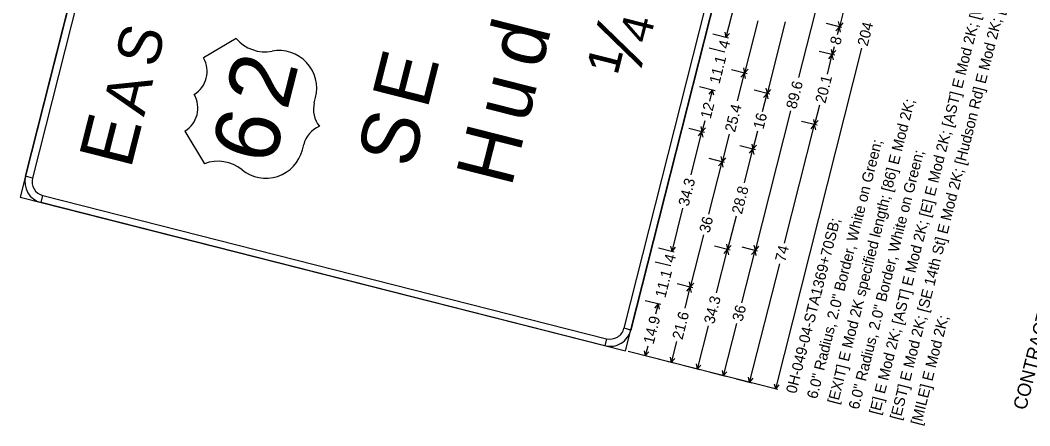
# Model space of a CAD drawing. Extents: x 670003 to 670131, y 737835 to 738003.
# Drawn here: x 670006.28 to 670053.15, y 737850.17 to 737868.98 of the extents above; entities that cross this region are included whole.
import ezdxf

# ---------------------------------------------------------------- set-up
doc = ezdxf.new("R2010")
doc.units = 0
doc.layers.add('R_SIGN', color=7, linetype='Continuous')

msp = doc.modelspace()

# ---------------------------------------------------------------- linework, layer by layer
at = {"layer": 'R_SIGN'}
for p, q in [((670014.634, 737893.727), (670006.276, 737860.771)), ((670034.386, 737853.641), (670042.744, 737886.598)), ((670042.425, 737866.321), (670044.064, 737872.783)), ((670044.932, 737871.133), (670044.308, 737868.675)), ((670039.547, 737870.187), (670039.038, 737868.182)), ((670040.519, 737868.947), (670039.903, 737866.52)), ((670041.794, 737868.904), (670040.951, 737865.581)), ((670044.429, 737868.645), (670043.704, 737868.828)), ((670044.255, 737868.919), (670044.308, 737868.675)), ((670044.471, 737868.864), (670044.308, 737868.675)), ((670039.159, 737868.152), (670038.434, 737868.335)), ((670038.985, 737868.426), (670039.038, 737868.182)), ((670039.201, 737868.371), (670039.038, 737868.182)), ((670044.145, 737868.486), (670044.308, 737868.675)), ((670044.217, 737868.317), (670044.308, 737868.675)), ((670044.361, 737868.432), (670044.308, 737868.675)), ((670016.302, 737868.135), (670014.783, 737867.231)), ((670038.995, 737867.505), (670038.27, 737867.689)), ((670045.343, 737867.682), (670041.335, 737851.879)), ((670044.101, 737867.352), (670043.376, 737867.536)), ((670043.753, 737866.485), (670043.98, 737867.383)), ((670043.817, 737867.194), (670043.98, 737867.383)), ((670043.927, 737867.626), (670043.98, 737867.383)), ((670044.071, 737867.741), (670043.98, 737867.383)), ((670044.143, 737867.571), (670043.98, 737867.383)), ((670044.034, 737867.139), (670043.98, 737867.383)), ((670040.024, 737866.49), (670039.299, 737866.674)), ((670039.578, 737865.24), (670039.903, 737866.52)), ((670039.74, 737866.332), (670039.903, 737866.52)), ((670039.85, 737866.764), (670039.903, 737866.52)), ((670040.066, 737866.709), (670039.903, 737866.52)), ((670039.956, 737866.277), (670039.903, 737866.52)), ((670038.541, 737865.712), (670037.815, 737865.896)), ((670038.257, 737865.554), (670038.42, 737865.743)), ((670038.289, 737865.228), (670038.42, 737865.743)), ((670038.473, 737865.499), (670038.42, 737865.743)), ((670041.072, 737865.55), (670040.347, 737865.734)), ((670040.74, 737864.748), (670040.951, 737865.581)), ((670040.788, 737865.392), (670040.951, 737865.581)), ((670040.898, 737865.824), (670040.951, 737865.581)), ((670041.114, 737865.769), (670040.951, 737865.581)), ((670041.004, 737865.337), (670040.951, 737865.581)), ((670019.93, 737865.152), (670019.992, 737865.394)), ((670043.385, 737865.033), (670043.157, 737864.136)), ((670042.032, 737864.77), (670040.393, 737858.308)), ((670037.875, 737864.048), (670037.928, 737863.804)), ((670038.058, 737864.319), (670037.928, 737863.804)), ((670041.762, 737858.637), (670043.157, 737864.136)), ((670043.278, 737864.105), (670042.553, 737864.289)), ((670042.994, 737863.947), (670043.157, 737864.136)), ((670043.104, 737864.379), (670043.157, 737864.136)), ((670043.32, 737864.324), (670043.157, 737864.136)), ((670043.21, 737863.892), (670043.157, 737864.136)), ((670013.923, 737863.838), (670014.827, 737862.319)), ((670038.049, 737863.774), (670037.324, 737863.957)), ((670037.42, 737861.802), (670037.928, 737863.804)), ((670037.765, 737863.615), (670037.928, 737863.804)), ((670038.091, 737863.993), (670037.928, 737863.804)), ((670037.981, 737863.561), (670037.928, 737863.804)), ((670039.186, 737863.694), (670038.862, 737862.414)), ((670040.507, 737863.828), (670040.295, 737862.996)), ((670019.377, 737862.971), (670019.439, 737863.213)), ((670040.416, 737862.965), (670039.691, 737863.149)), ((670040.242, 737863.239), (670040.295, 737862.996)), ((670040.458, 737863.184), (670040.295, 737862.996)), ((670038.808, 737862.657), (670038.862, 737862.414)), ((670039.902, 737861.444), (670040.295, 737862.996)), ((670040.132, 737862.807), (670040.295, 737862.996)), ((670040.349, 737862.752), (670040.295, 737862.996)), ((670038.246, 737859.987), (670038.862, 737862.414)), ((670038.982, 737862.383), (670038.257, 737862.567)), ((670038.699, 737862.225), (670038.862, 737862.414)), ((670039.024, 737862.602), (670038.862, 737862.414)), ((670038.915, 737862.17), (670038.862, 737862.414)), ((670006.845, 737861.658), (670006.522, 737861.74)), ((670006.276, 737860.771), (670034.386, 737853.641)), ((670007.245, 737860.525), (670007.327, 737860.848)), ((670037.03, 737860.262), (670036.522, 737858.26)), ((670039.509, 737859.894), (670039.115, 737858.343)), ((670038.002, 737859.024), (670037.387, 737856.598)), ((670036.469, 737858.503), (670036.522, 737858.26)), ((670036.685, 737858.448), (670036.522, 737858.26)), ((670039.236, 737858.312), (670038.511, 737858.496)), ((670039.062, 737858.587), (670039.115, 737858.343)), ((670039.278, 737858.532), (670039.115, 737858.343)), ((670040.513, 737858.277), (670039.788, 737858.461)), ((670040.339, 737858.552), (670040.393, 737858.308)), ((670040.556, 737858.497), (670040.393, 737858.308)), ((670036.643, 737858.229), (670035.918, 737858.413)), ((670038.608, 737856.341), (670039.115, 737858.343)), ((670038.952, 737858.154), (670039.115, 737858.343)), ((670039.169, 737858.099), (670039.115, 737858.343)), ((670039.777, 737855.881), (670040.393, 737858.308)), ((670040.23, 737858.119), (670040.393, 737858.308)), ((670040.446, 737858.064), (670040.393, 737858.308)), ((670036.479, 737857.583), (670035.754, 737857.767)), ((670041.521, 737857.684), (670040.126, 737852.186)), ((670037.507, 737856.567), (670036.782, 737856.751)), ((670037.141, 737855.629), (670037.387, 737856.598)), ((670037.224, 737856.409), (670037.387, 737856.598)), ((670037.333, 737856.841), (670037.387, 737856.598)), ((670037.549, 737856.787), (670037.387, 737856.598)), ((670037.44, 737856.354), (670037.387, 737856.598)), ((670036.024, 737855.79), (670035.299, 737855.974)), ((670035.74, 737855.632), (670035.903, 737855.82)), ((670035.787, 737855.364), (670035.903, 737855.82)), ((670035.956, 737855.577), (670035.903, 737855.82)), ((670034.632, 737854.611), (670034.309, 737854.693)), ((670038.217, 737854.801), (670037.709, 737852.799)), ((670039.533, 737854.919), (670038.918, 737852.492)), ((670033.499, 737854.21), (670033.417, 737853.887)), ((670035.408, 737853.867), (670035.292, 737853.412)), ((670036.746, 737854.074), (670036.501, 737853.105)), ((670034.386, 737853.641), (670034.386, 737853.641)), ((670041.455, 737851.848), (670034.507, 737853.611)), ((670035.413, 737853.381), (670034.688, 737853.565)), ((670035.239, 737853.655), (670035.292, 737853.412)), ((670035.455, 737853.6), (670035.292, 737853.412)), ((670036.447, 737853.349), (670036.501, 737853.105)), ((670036.664, 737853.294), (670036.501, 737853.105)), ((670036.622, 737853.074), (670035.896, 737853.258)), ((670037.83, 737852.768), (670037.105, 737852.952)), ((670037.656, 737853.042), (670037.709, 737852.799)), ((670037.872, 737852.987), (670037.709, 737852.799)), ((670039.038, 737852.461), (670038.313, 737852.645)), ((670038.864, 737852.736), (670038.918, 737852.492)), ((670039.08, 737852.681), (670038.918, 737852.492)), ((670040.247, 737852.155), (670039.522, 737852.339)), ((670040.073, 737852.429), (670040.126, 737852.186)), ((670040.289, 737852.374), (670040.126, 737852.186)), ((670041.281, 737852.123), (670041.335, 737851.879)), ((670041.497, 737852.068), (670041.335, 737851.879))]:
    msp.add_line(p, q, dxfattribs=at)
for points in [[(670014.712, 737892.676), (670006.845, 737861.658), (670006.522, 737861.74), (670014.389, 737892.758), (670014.712, 737892.676)], [(670034.309, 737854.693), (670042.175, 737885.711), (670042.499, 737885.629), (670034.632, 737854.611), (670034.309, 737854.693)], [(670007.327, 737860.848), (670033.499, 737854.21), (670033.417, 737853.887), (670007.245, 737860.525), (670007.327, 737860.848)]]:
    msp.add_lwpolyline(points, close=True, dxfattribs=at)
for centre, radius, start, end in [((670017.641, 737869.263), 1.75, 220.1058, 280.7786), ((670018.295, 737865.824), 1.75, 345.7686, 100.779), ((670013.703, 737866.602), 1.25, 301.3415, 30.1958), ((670013.273, 737864.906), 1.25, 301.3415, 30.1958), ((670021.142, 737864.844), 1.25, 165.7688, 218.8986), ((670020.65, 737862.906), 1.25, 112.6384, 165.7688), ((670017.681, 737863.401), 1.75, 230.7582, 345.7686), ((670015.467, 737860.69), 1.75, 50.7581, 111.4314), ((670007.491, 737861.494), 1, 165.7688, 255.7684), ((670007.491, 737861.494), 0.667, 165.7688, 255.7684), ((670033.662, 737854.857), 0.667, 255.7684, 345.7686), ((670033.662, 737854.857), 1, 255.7684, 345.7686)]:
    msp.add_arc(centre, radius, start, end, dxfattribs=at)

# ---------------------------------------------------------------- texts
for s, height, p in [('CONTRACTOR SHALL BE RESPONSIBLE FOR FIELD VERIFICATION OF', 0.625, (670052.971, 737850.867)), ('[E] E Mod 2K; [AST] E Mod 2K; [E] E Mod 2K; [AST] E Mod 2K; [W] E Mod 2K; ', 0.49869, (670046.168, 737850.653)), ('[EST] E Mod 2K; [SE 14th St] E Mod 2K; [Hudson Rd] E Mod 2K; [¼] E Mod 2K; ', 0.49869, (670047.135, 737850.408)), ('d', 2.667, (670030.457, 737866.66)), ('¼', 2.5, (670034.985, 737866.208)), ('204', 0.4987, (670045.615, 737867.742)), ('S', 2, (670012.591, 737866.723)), ('4', 0.499, (670039.154, 737867.624)), ('8', 0.499, (670044.344, 737867.801)), ('E', 2.667, (670025.17, 737864.796)), ('2', 3, (670018.668, 737864.75)), ('11.1', 0.4987, (670038.742, 737866)), ('A', 2, (670012.021, 737864.474)), ('u', 2.667, (670029.822, 737864.153)), ('89.6', 0.4987, (670042.304, 737864.83)), ('20.1', 0.4987, (670043.657, 737865.093)), ('12', 0.4987, (670038.331, 737864.378)), ('25.4', 0.4987, (670039.459, 737863.754)), ('[EXIT] E Mod 2K specified length; [86] E Mod 2K; ', 0.49869, (670044.235, 737851.144)), ('E', 2.5, (670011.402, 737862.034)), ('6', 3, (670018.019, 737862.191)), ('S', 2.667, (670024.475, 737862.056)), ('16', 0.4987, (670040.779, 737863.888)), ('H', 2.667, (670029.068, 737861.18)), ('6.0" Radius, 2.0" Border, White on Green; ', 0.49869, (670043.268, 737851.389)), ('6.0" Radius, 2.0" Border, White on Green; ', 0.49869, (670045.202, 737850.898)), ('34.3', 0.4987, (670037.302, 737860.322)), ('28.8', 0.4987, (670039.781, 737859.954)), ('36', 0.4987, (670038.274, 737859.084)), ('0H-049-04-STA1369+70SB; ', 0.49869, (670042.301, 737851.634)), ('74', 0.4987, (670041.793, 737857.744)), ('4', 0.499, (670036.638, 737857.702)), ('11.1', 0.4987, (670036.226, 737856.077)), ('34.3', 0.4987, (670038.489, 737854.86)), ('36', 0.4987, (670039.805, 737854.978)), ('14.9', 0.4987, (670035.68, 737853.927)), ('21.6', 0.4987, (670037.019, 737854.133)), ('[MILE] E Mod 2K; ', 0.49869, (670048.102, 737850.163))]:
    msp.add_text(s, height=height, rotation=75.7686, dxfattribs=at).set_placement(p)

doc.saveas('drawing.dxf')
